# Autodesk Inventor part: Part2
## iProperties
Created: 2018-06
Part Number: Part2
Document SubType Name: Modeling
Designer: M.Shelton
Density: 1 g/cm^3
Author: M.Shelton
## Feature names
1. Extrusion1
2. Revolution1
3. Revolution2
4. Fillet1
